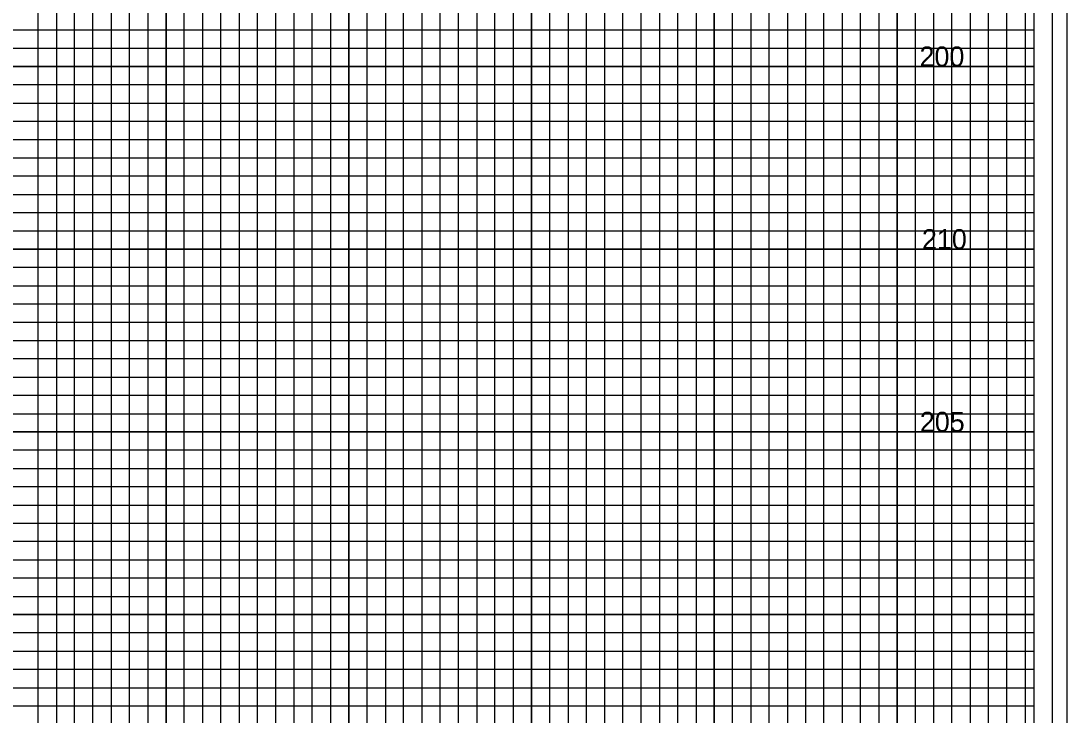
# Model space of a CAD drawing. Extents: x -4 to 103, y -2 to 351.
# Drawn here: x 74.78 to 103.4, y 244.73 to 263.73 of the extents above; entities that cross this region are included whole.
import ezdxf

# ---------------------------------------------------------------- set-up
doc = ezdxf.new("R2010")
doc.units = 0
for name, color, linetype in [('Old_Level_10', 7, 'Continuous'), ('Old_Level_4', 7, 'Continuous'), ('Old_Level_5', 7, 'Continuous'), ('Old_Level_6', 7, 'Continuous'), ('Old_Level_8', 7, 'Continuous'), ('Prop XS Finish Grade', 7, 'Continuous'), ('Prop XS SE Text', 7, 'Continuous')]:
    doc.layers.add(name, color=color, linetype=linetype)

msp = doc.modelspace()

# ---------------------------------------------------------------- linework, layer by layer
at = {"layer": 'Old_Level_10'}
for p, q in [((91.25, 212.475), (91.25, 275.9)), ((93.75, 212.475), (93.75, 275.9)), ((96.25, 212.475), (96.25, 275.9)), ((98.75, 212.475), (98.75, 275.9)), ((101.25, 212.475), (101.25, 275.9)), ((76.25, 212.475), (76.25, 274.475)), ((78.75, 212.475), (78.75, 274.475)), ((81.25, 212.475), (81.25, 274.475)), ((83.75, 212.475), (83.75, 274.475)), ((86.25, 212.475), (86.25, 274.475)), ((88.75, 212.475), (88.75, 274.475)), ((0, 262.475), (102.5, 262.475)), ((0, 259.975), (102.5, 259.975)), ((0, 257.475), (102.5, 257.475)), ((0, 254.975), (102.5, 254.975)), ((0, 252.475), (102.5, 252.475)), ((0, 249.975), (102.5, 249.975)), ((0, 247.475), (102.5, 247.475)), ((0, 244.975), (102.5, 244.975))]:
    msp.add_line(p, q, dxfattribs=at)
at = {"layer": 'Old_Level_4'}
for points in [[(90.25, 212.475), (90.25, 275.9), (90.75, 275.9), (90.75, 212.475)], [(91.75, 212.475), (91.75, 275.9), (92.25, 275.9), (92.25, 212.475)], [(92.75, 212.475), (92.75, 275.9), (93.25, 275.9), (93.25, 212.475)], [(94.25, 212.475), (94.25, 275.9), (94.75, 275.9), (94.75, 212.475)], [(95.25, 212.475), (95.25, 275.9), (95.75, 275.9), (95.75, 212.475)], [(96.75, 212.475), (96.75, 275.9), (97.25, 275.9), (97.25, 212.475)], [(97.75, 212.475), (97.75, 275.9), (98.25, 275.9), (98.25, 212.475)], [(99.25, 212.475), (99.25, 275.9), (99.75, 275.9), (99.75, 212.475)], [(100.25, 212.475), (100.25, 275.9)], [(100.25, 275.9), (100.75, 275.9), (100.75, 212.475), (101.75, 212.475), (101.75, 275.9), (102.25, 275.9), (102.25, 212.475)], [(75.25, 212.475), (75.25, 274.475), (75.75, 274.475), (75.75, 212.475)], [(76.75, 212.475), (76.75, 274.475), (77.25, 274.475), (77.25, 212.475)], [(77.75, 212.475), (77.75, 274.475), (78.25, 274.475), (78.25, 212.475)], [(79.25, 212.475), (79.25, 274.475), (79.75, 274.475), (79.75, 212.475)], [(80.25, 212.475), (80.25, 274.475), (80.75, 274.475), (80.75, 212.475)], [(81.75, 212.475), (81.75, 274.475), (82.25, 274.475), (82.25, 212.475)], [(82.75, 212.475), (82.75, 274.475), (83.25, 274.475), (83.25, 212.475)], [(84.25, 212.475), (84.25, 274.475), (84.75, 274.475), (84.75, 212.475)], [(85.25, 212.475), (85.25, 274.475), (85.75, 274.475), (85.75, 212.475)], [(86.75, 212.475), (86.75, 274.475), (87.25, 274.475), (87.25, 212.475)], [(87.75, 212.475), (87.75, 274.475), (88.25, 274.475), (88.25, 212.475)], [(89.25, 212.475), (89.25, 274.475), (89.75, 274.475), (89.75, 212.475)], [(0, 262.975), (102.5, 262.975), (102.5, 263.475), (0, 263.475)], [(0, 261.475), (102.5, 261.475), (102.5, 261.975), (0, 261.975)], [(0, 260.475), (102.5, 260.475), (102.5, 260.975), (0, 260.975)], [(0, 258.975), (102.5, 258.975), (102.5, 259.475), (0, 259.475)], [(0, 257.975), (102.5, 257.975), (102.5, 258.475), (0, 258.475)], [(0, 256.475), (102.5, 256.475), (102.5, 256.975), (0, 256.975)], [(0, 255.475), (102.5, 255.475), (102.5, 255.975), (0, 255.975)], [(0, 253.975), (102.5, 253.975), (102.5, 254.475), (0, 254.475)], [(0, 252.975), (102.5, 252.975), (102.5, 253.475), (0, 253.475)], [(0, 251.475), (102.5, 251.475), (102.5, 251.975), (0, 251.975)], [(0, 250.475), (102.5, 250.475), (102.5, 250.975), (0, 250.975)], [(0, 248.975), (102.5, 248.975), (102.5, 249.475), (0, 249.475)], [(0, 247.975), (102.5, 247.975), (102.5, 248.475), (0, 248.475)], [(0, 246.475), (102.5, 246.475), (102.5, 246.975), (0, 246.975)], [(0, 245.475), (102.5, 245.475), (102.5, 245.975), (0, 245.975)]]:
    msp.add_lwpolyline(points, dxfattribs=at)
at = {"layer": 'Old_Level_5'}
msp.add_lwpolyline([(103.4, 279.875), (-3.5, 279.875), (-3.5, 210.05), (103.4, 210.05)], close=True, dxfattribs=at)
at = {"layer": 'Old_Level_6'}
msp.add_lwpolyline([(102.5, 277.475), (0, 277.475), (0, 212.475), (102.5, 212.475)], close=True, dxfattribs=at)
at = {"layer": 'Old_Level_8'}
for points in [[(91.25, 212.475), (91.25, 275.9), (93.75, 275.9), (93.75, 212.475)], [(96.25, 212.475), (96.25, 275.9), (98.75, 275.9), (98.75, 212.475)], [(101.25, 212.475), (101.25, 275.9)], [(76.25, 212.475), (76.25, 274.475), (78.75, 274.475), (78.75, 212.475)], [(81.25, 212.475), (81.25, 274.475), (83.75, 274.475), (83.75, 212.475)], [(86.25, 212.475), (86.25, 274.475), (88.75, 274.475), (88.75, 212.475)], [(0, 259.975), (102.5, 259.975), (102.5, 262.475), (0, 262.475)], [(0, 254.975), (102.5, 254.975), (102.5, 257.475), (0, 257.475)], [(0, 249.975), (102.5, 249.975), (102.5, 252.475), (0, 252.475)], [(0, 244.975), (102.5, 244.975), (102.5, 247.475), (0, 247.475)]]:
    msp.add_lwpolyline(points, dxfattribs=at)
at = {"layer": 'Prop XS SE Text'}
msp.add_lwpolyline([(103, 278.475), (-2.8, 278.475), (-2.8, 211.475), (103, 211.475)], close=True, dxfattribs=at)

# ---------------------------------------------------------------- texts
at = {"layer": 'Prop XS Finish Grade'}
for s, p in [('200', (99.3638, 262.475)), ('210', (99.4296, 257.475)), ('205', (99.3724, 252.475))]:
    msp.add_text(s, height=0.55, dxfattribs=at).set_placement(p)

doc.saveas('drawing.dxf')
